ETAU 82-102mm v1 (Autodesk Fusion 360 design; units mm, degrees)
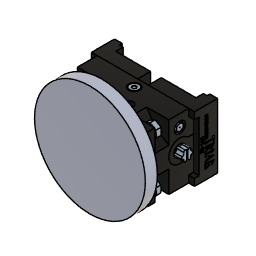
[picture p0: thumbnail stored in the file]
parameter "Ouverture" = 95
base_feature "Base Feature1"
joint_origin "JointOrigin1" OffsetX 0 OffsetY 0 OffsetZ 0
base_feature "Base Feature1"
joint_origin "JointOrigin1" OffsetX 0 OffsetY 0 OffsetZ 0
joint_origin "JointOrigin2" OffsetX 0 OffsetY 0 OffsetZ 0
base_feature "Base Feature1"
joint "Assemble1" alignOffsetX 0 alignOffsetY 0 alignOffsetZ 5.8 (= "Ouverture / 2 - 41.7 mm")
joint "Assemble2" alignOffsetX 0 alignOffsetY 0 alignOffsetZ -5.8 (= "-Ouverture / 2 + 41.7 mm")
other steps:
create_component "CreateComponent1"
create_component "CreateComponent2"
create_component "CreateComponent3"
joint_origin "JointOrigin2" OffsetX 0 OffsetY 0 OffsetZ 0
